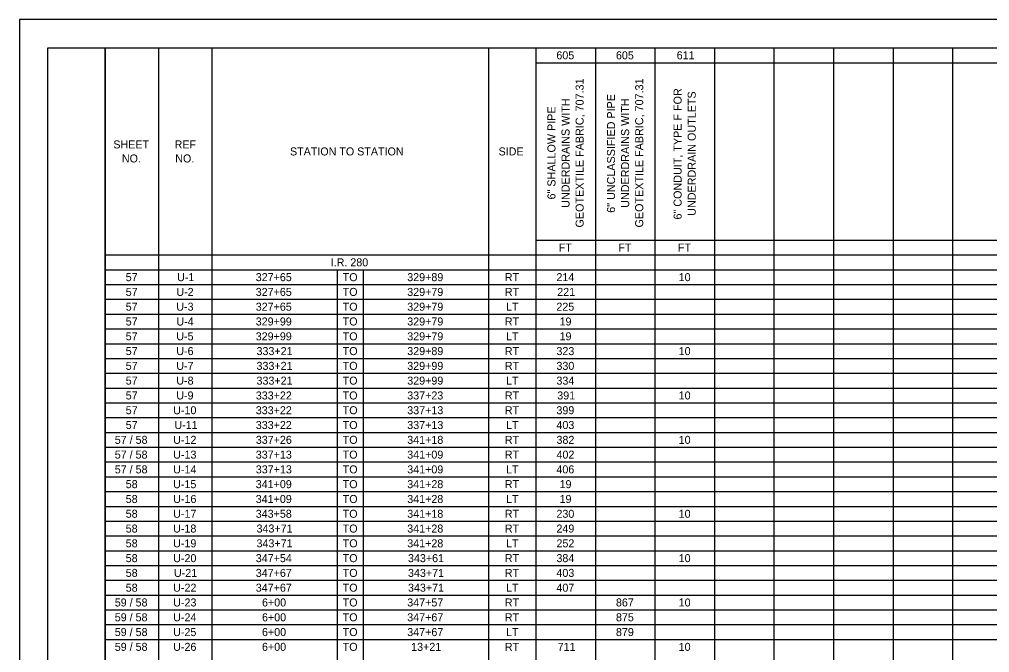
# Model space of a CAD drawing. Extents: x 0 to 34, y 0 to 22.
# Drawn here: x 0 to 17, y 10.9 to 22 of the extents above; entities that cross this region are included whole.
import ezdxf

# ---------------------------------------------------------------- set-up
doc = ezdxf.new("R2010")
doc.units = 0
for name, color, linetype in [('SH_Border', 7, 'Continuous'), ('SH_Cut_Line', 7, 'Continuous'), ('SH_Text', 7, 'Continuous')]:
    doc.layers.add(name, color=color, linetype=linetype)

msp = doc.modelspace()

# ---------------------------------------------------------------- linework, layer by layer
at = {"layer": 'SH_Border'}
for points in [[(0.5, 21.5), (1.5, 21.5), (1.5, 0.5), (0.5, 0.5)], [(1.5, 21.5), (33.5, 21.5), (33.5, 0.5), (1.5, 0.5)]]:
    msp.add_lwpolyline(points, close=True, dxfattribs=at)
at = {"layer": 'SH_Cut_Line'}
msp.add_lwpolyline([(0, 0), (34, 0), (34, 22), (0, 22)], close=True, dxfattribs=at)
at = {"layer": 'SH_Text'}
for p, q in [((1.5, 21.5), (32, 21.5)), ((1.5, 21.5), (1.5, 0.5)), ((2.436, 21.5), (2.436, 0.759)), ((3.372, 21.5), (3.372, 0.759)), ((8.22, 21.5), (8.22, 0.759)), ((9.048, 21.5), (9.048, 0.5)), ((10.092, 21.5), (10.092, 0.5)), ((11.135, 21.5), (11.135, 0.5)), ((12.178, 21.5), (12.178, 0.5)), ((13.221, 21.5), (13.221, 0.5)), ((14.265, 21.5), (14.265, 0.5)), ((15.308, 21.5), (15.308, 0.5)), ((16.351, 21.5), (16.351, 0.5)), ((9.048, 21.241), (32, 21.241)), ((9.048, 18.13), (32, 18.13)), ((1.5, 17.87), (32, 17.87)), ((1.5, 17.611), (32, 17.611)), ((5.566, 17.611), (5.566, 0.759)), ((6.026, 17.611), (6.026, 0.759)), ((1.5, 17.352), (32, 17.352)), ((1.5, 17.093), (32, 17.093)), ((1.5, 16.833), (32, 16.833)), ((1.5, 16.574), (32, 16.574)), ((1.5, 16.315), (32, 16.315)), ((1.5, 16.056), (32, 16.056)), ((1.5, 15.796), (32, 15.796)), ((1.5, 15.537), (32, 15.537)), ((1.5, 15.278), (32, 15.278)), ((1.5, 15.019), (32, 15.019)), ((1.5, 14.759), (32, 14.759)), ((1.5, 14.5), (32, 14.5)), ((1.5, 14.241), (32, 14.241)), ((1.5, 13.981), (32, 13.981)), ((1.5, 13.722), (32, 13.722)), ((1.5, 13.463), (32, 13.463)), ((1.5, 13.204), (32, 13.204)), ((1.5, 12.944), (32, 12.944)), ((1.5, 12.685), (32, 12.685)), ((1.5, 12.426), (32, 12.426)), ((1.5, 12.167), (32, 12.167)), ((1.5, 11.907), (32, 11.907)), ((1.5, 11.648), (32, 11.648)), ((1.5, 11.389), (32, 11.389)), ((1.5, 11.13), (32, 11.13))]:
    msp.add_line(p, q, dxfattribs=at)

# ---------------------------------------------------------------- texts
for s, height, p in [('605', 0.1403, (9.409, 21.3)), ('605', 0.1403, (10.453, 21.3)), ('611', 0.1403, (11.517, 21.3)), ('SHEET ', 0.1403, (1.646, 19.738)), ('REF    ', 0.1403, (2.72, 19.738)), ('STATION TO STATION', 0.14031, (4.741, 19.615)), ('SIDE', 0.1403, (8.396, 19.615)), ('NO.', 0.1403, (1.796, 19.492)), ('NO.', 0.1403, (2.731, 19.492)), ('FT', 0.1403, (9.451, 17.93)), ('FT', 0.1403, (10.495, 17.93)), ('FT', 0.1403, (11.538, 17.93)), ('I.R. 280', 0.1403, (5.455, 17.671)), ('57', 0.1403, (1.863, 17.411)), ('U-1', 0.1403, (2.763, 17.411)), ('327+65', 0.1403, (4.141, 17.411)), ('TO', 0.1403, (5.665, 17.411)), ('329+89', 0.1403, (6.796, 17.411)), ('RT', 0.1403, (8.506, 17.411)), ('214', 0.1403, (9.41, 17.411)), ('10', 0.1403, (11.552, 17.411)), ('57', 0.1403, (1.863, 17.152)), ('U-2', 0.1403, (2.75, 17.152)), ('327+65', 0.1403, (4.141, 17.152)), ('TO', 0.1403, (5.665, 17.152)), ('329+79', 0.1403, (6.796, 17.152)), ('RT', 0.1403, (8.506, 17.152)), ('221', 0.1403, (9.424, 17.152)), ('57', 0.1403, (1.863, 16.893)), ('U-3', 0.1403, (2.749, 16.893)), ('327+65', 0.1403, (4.141, 16.893)), ('TO', 0.1403, (5.665, 16.893)), ('329+79', 0.1403, (6.796, 16.893)), ('LT', 0.1403, (8.528, 16.893)), ('225', 0.1403, (9.409, 16.893)), ('57', 0.1403, (1.863, 16.634)), ('U-4', 0.1403, (2.75, 16.634)), ('329+99', 0.1403, (4.141, 16.634)), ('TO', 0.1403, (5.665, 16.634)), ('329+79', 0.1403, (6.796, 16.634)), ('RT', 0.1403, (8.506, 16.634)), ('19', 0.1403, (9.465, 16.634)), ('57', 0.1403, (1.863, 16.374)), ('U-5', 0.1403, (2.749, 16.374)), ('329+99', 0.1403, (4.141, 16.374)), ('TO', 0.1403, (5.665, 16.374)), ('329+79', 0.1403, (6.796, 16.374)), ('LT', 0.1403, (8.528, 16.374)), ('19', 0.1403, (9.465, 16.374)), ('57', 0.1403, (1.863, 16.115)), ('U-6', 0.1403, (2.749, 16.115)), ('333+21', 0.1403, (4.155, 16.115)), ('TO', 0.1403, (5.665, 16.115)), ('329+89', 0.1403, (6.796, 16.115)), ('RT', 0.1403, (8.506, 16.115)), ('323', 0.1403, (9.41, 16.115)), ('10', 0.1403, (11.552, 16.115)), ('57', 0.1403, (1.863, 15.856)), ('U-7', 0.1403, (2.749, 15.856)), ('333+21', 0.1403, (4.155, 15.856)), ('TO', 0.1403, (5.665, 15.856)), ('329+99', 0.1403, (6.796, 15.856)), ('RT', 0.1403, (8.506, 15.856)), ('330', 0.1403, (9.41, 15.856)), ('57', 0.1403, (1.863, 15.597)), ('U-8', 0.1403, (2.749, 15.597)), ('333+21', 0.1403, (4.155, 15.597)), ('TO', 0.1403, (5.665, 15.597)), ('329+99', 0.1403, (6.796, 15.597)), ('LT', 0.1403, (8.528, 15.597)), ('334', 0.1403, (9.41, 15.597)), ('57', 0.1403, (1.863, 15.337)), ('U-9', 0.1403, (2.749, 15.337)), ('333+22', 0.1403, (4.142, 15.337)), ('TO', 0.1403, (5.665, 15.337)), ('337+23', 0.1403, (6.796, 15.337)), ('RT', 0.1403, (8.506, 15.337)), ('391', 0.1403, (9.424, 15.337)), ('10', 0.1403, (11.552, 15.337)), ('57', 0.1403, (1.863, 15.078)), ('U-10', 0.1403, (2.695, 15.078)), ('333+22', 0.1403, (4.142, 15.078)), ('TO', 0.1403, (5.665, 15.078)), ('337+13', 0.1403, (6.796, 15.078)), ('RT', 0.1403, (8.506, 15.078)), ('399', 0.1403, (9.41, 15.078)), ('333+22', 0.1403, (4.142, 14.819)), ('TO', 0.1403, (5.665, 14.819)), ('337+13', 0.1403, (6.796, 14.819)), ('403', 0.1403, (9.41, 14.819)), ('57', 0.1403, (1.863, 14.819)), ('U-11', 0.1403, (2.716, 14.819)), ('LT', 0.1403, (8.528, 14.819)), ('57 / 58', 0.1403, (1.671, 14.559)), ('U-12', 0.1403, (2.695, 14.559)), ('337+26', 0.1403, (4.142, 14.559)), ('TO', 0.1403, (5.665, 14.559)), ('341+18', 0.1403, (6.796, 14.559)), ('RT', 0.1403, (8.506, 14.559)), ('382', 0.1403, (9.411, 14.559)), ('10', 0.1403, (11.552, 14.559)), ('57 / 58', 0.1403, (1.671, 14.3)), ('U-13', 0.1403, (2.695, 14.3)), ('337+13', 0.1403, (4.142, 14.3)), ('TO', 0.1403, (5.665, 14.3)), ('341+09', 0.1403, (6.796, 14.3)), ('RT', 0.1403, (8.506, 14.3)), ('402', 0.1403, (9.411, 14.3)), ('57 / 58', 0.1403, (1.671, 14.041)), ('U-14', 0.1403, (2.695, 14.041)), ('337+13', 0.1403, (4.142, 14.041)), ('TO', 0.1403, (5.665, 14.041)), ('341+09', 0.1403, (6.796, 14.041)), ('LT', 0.1403, (8.528, 14.041)), ('406', 0.1403, (9.41, 14.041)), ('58', 0.1403, (1.863, 13.782)), ('U-15', 0.1403, (2.694, 13.782)), ('341+09', 0.1403, (4.141, 13.782)), ('TO', 0.1403, (5.665, 13.782)), ('341+28', 0.1403, (6.796, 13.782)), ('RT', 0.1403, (8.506, 13.782)), ('19', 0.1403, (9.465, 13.782)), ('58', 0.1403, (1.863, 13.522)), ('U-16', 0.1403, (2.695, 13.522)), ('341+09', 0.1403, (4.141, 13.522)), ('TO', 0.1403, (5.665, 13.522)), ('341+28', 0.1403, (6.796, 13.522)), ('LT', 0.1403, (8.528, 13.522)), ('19', 0.1403, (9.465, 13.522)), ('58', 0.1403, (1.863, 13.263)), ('U-17', 0.1403, (2.695, 13.263)), ('343+58', 0.1403, (4.141, 13.263)), ('TO', 0.1403, (5.665, 13.263)), ('341+18', 0.1403, (6.796, 13.263)), ('RT', 0.1403, (8.506, 13.263)), ('230', 0.1403, (9.41, 13.263)), ('10', 0.1403, (11.552, 13.263)), ('58', 0.1403, (1.863, 13.004)), ('U-18', 0.1403, (2.694, 13.004)), ('343+71', 0.1403, (4.155, 13.004)), ('TO', 0.1403, (5.665, 13.004)), ('341+28', 0.1403, (6.796, 13.004)), ('RT', 0.1403, (8.506, 13.004)), ('249', 0.1403, (9.41, 13.004)), ('58', 0.1403, (1.863, 12.745)), ('U-19', 0.1403, (2.694, 12.745)), ('343+71', 0.1403, (4.155, 12.745)), ('TO', 0.1403, (5.665, 12.745)), ('341+28', 0.1403, (6.796, 12.745)), ('LT', 0.1403, (8.528, 12.745)), ('252', 0.1403, (9.411, 12.745)), ('58', 0.1403, (1.863, 12.485)), ('U-20', 0.1403, (2.695, 12.485)), ('347+54', 0.1403, (4.142, 12.485)), ('TO', 0.1403, (5.665, 12.485)), ('343+61', 0.1403, (6.809, 12.485)), ('RT', 0.1403, (8.506, 12.485)), ('384', 0.1403, (9.41, 12.485)), ('10', 0.1403, (11.552, 12.485)), ('58', 0.1403, (1.863, 12.226)), ('U-21', 0.1403, (2.708, 12.226)), ('347+67', 0.1403, (4.142, 12.226)), ('TO', 0.1403, (5.665, 12.226)), ('343+71', 0.1403, (6.809, 12.226)), ('RT', 0.1403, (8.506, 12.226)), ('403', 0.1403, (9.41, 12.226)), ('58', 0.1403, (1.863, 11.967)), ('U-22', 0.1403, (2.695, 11.967)), ('347+67', 0.1403, (4.142, 11.967)), ('TO', 0.1403, (5.665, 11.967)), ('343+71', 0.1403, (6.809, 11.967)), ('LT', 0.1403, (8.528, 11.967)), ('407', 0.1403, (9.41, 11.967)), ('59 / 58', 0.1403, (1.671, 11.708)), ('U-23', 0.1403, (2.695, 11.708)), ('6+00', 0.1403, (4.251, 11.708)), ('TO', 0.1403, (5.665, 11.708)), ('347+57', 0.1403, (6.796, 11.708)), ('RT', 0.1403, (8.506, 11.708)), ('867', 0.1403, (10.453, 11.708)), ('10', 0.1403, (11.552, 11.708)), ('59 / 58', 0.1403, (1.671, 11.448)), ('U-24', 0.1403, (2.695, 11.448)), ('6+00', 0.1403, (4.251, 11.448)), ('TO', 0.1403, (5.665, 11.448)), ('347+67', 0.1403, (6.796, 11.448)), ('RT', 0.1403, (8.506, 11.448)), ('875', 0.1403, (10.453, 11.448)), ('59 / 58', 0.1403, (1.671, 11.189)), ('U-25', 0.1403, (2.694, 11.189)), ('6+00', 0.1403, (4.251, 11.189)), ('TO', 0.1403, (5.665, 11.189)), ('347+67', 0.1403, (6.796, 11.189)), ('LT', 0.1403, (8.528, 11.189)), ('879', 0.1403, (10.453, 11.189)), ('59 / 58', 0.1403, (1.671, 10.93)), ('U-26', 0.1403, (2.695, 10.93)), ('6+00', 0.1403, (4.251, 10.93)), ('TO', 0.1403, (5.665, 10.93)), ('13+21', 0.1403, (6.864, 10.93)), ('RT', 0.1403, (8.506, 10.93)), ('711', 0.1403, (9.431, 10.93)), ('10', 0.1403, (11.552, 10.93))]:
    msp.add_text(s, height=height, dxfattribs=at).set_placement(p)
for s, p in [('GEOTEXTILE FABRIC, 707.31', (9.887, 18.352)), ('GEOTEXTILE FABRIC, 707.31', (10.931, 18.352)), ('6" CONDUIT, TYPE F FOR ', (11.604, 18.492)), ('UNDERDRAINS WITH ', (9.64, 18.697)), ('6" UNCLASSIFIED PIPE ', (10.437, 18.61)), ('UNDERDRAINS WITH ', (10.684, 18.697)), ('UNDERDRAIN OUTLETS', (11.851, 18.557)), ('6" SHALLOW PIPE ', (9.393, 18.844))]:
    msp.add_text(s, height=0.14115, rotation=90, dxfattribs=at).set_placement(p)

doc.saveas('drawing.dxf')
